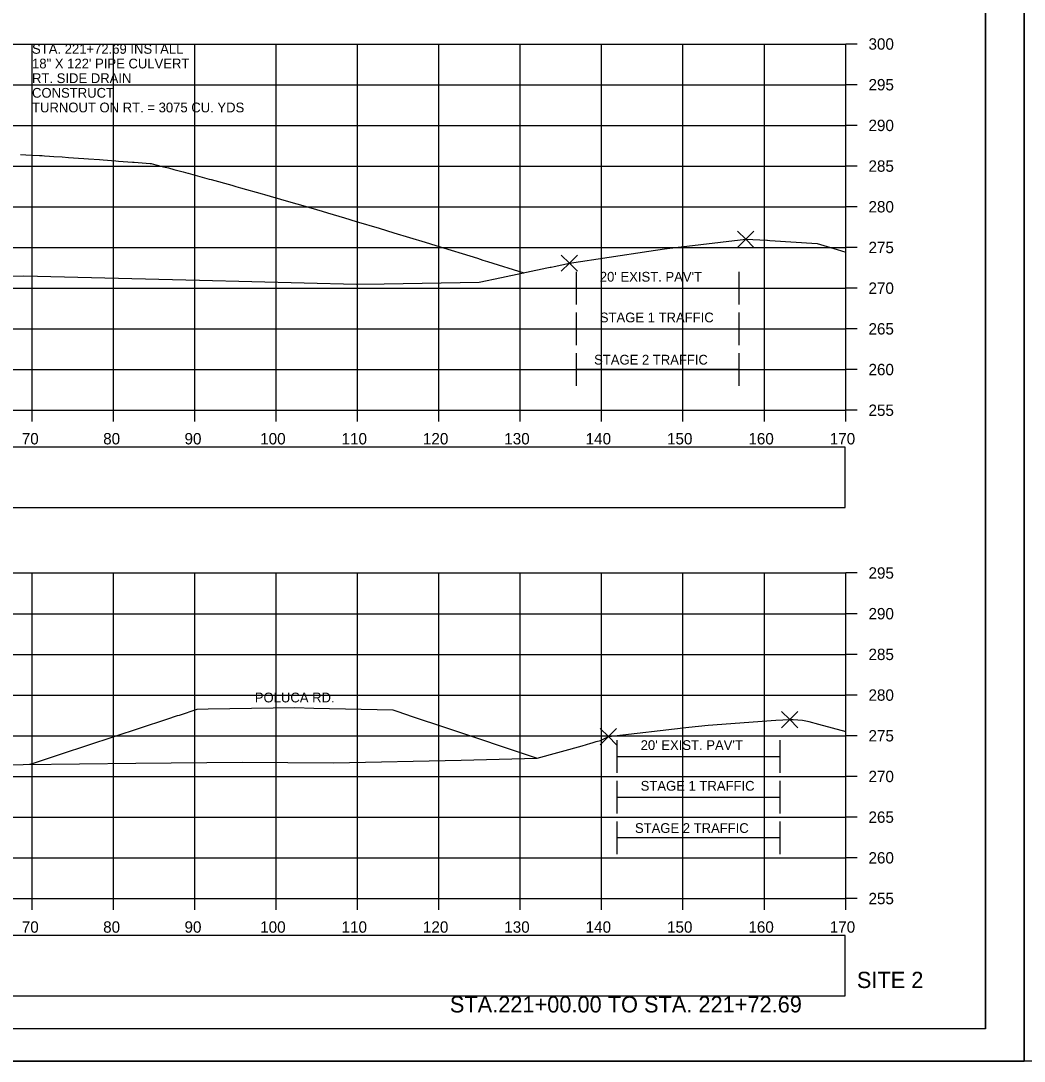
# Model space of a CAD drawing. Extents: x 4667 to 1632277, y -2100 to 724501.
# Drawn here: x 5845.8 to 5969.1, y -683.7 to -555.9 of the extents above; entities that cross this region are included whole.
import ezdxf

# ---------------------------------------------------------------- set-up
doc = ezdxf.new("R2010")
doc.units = 0
for name, color, linetype in [('R_Axis', 7, 'Continuous'), ('R_Axis Annot', 7, 'Continuous'), ('R_Border', 7, 'Continuous'), ('R_Draft', 7, 'Continuous'), ('R_Drive', 7, 'Continuous'), ('R_Exist Surface', 7, 'Continuous'), ('R_Fin Surface', 7, 'Continuous'), ('R_Grid', 7, 'Continuous'), ('R_No Plot', 7, 'Continuous'), ('R_Proposed CofA', 7, 'Continuous'), ('R_Temp Easement', 7, 'Continuous'), ('R_Water Annot', 7, 'Continuous')]:
    doc.layers.add(name, color=color, linetype=linetype)

msp = doc.modelspace()

# ---------------------------------------------------------------- linework, layer by layer
at = {"layer": 'R_Axis'}
for p, q in [((5947.18, -603.75), (5947.18, -558.75)), ((5948.58, -558.75), (5947.18, -558.75)), ((5948.58, -563.75), (5947.18, -563.75)), ((5948.58, -568.75), (5947.18, -568.75)), ((5948.58, -573.75), (5947.18, -573.75)), ((5948.58, -578.75), (5947.18, -578.75)), ((5948.58, -583.75), (5947.18, -583.75)), ((5948.58, -588.75), (5947.18, -588.75)), ((5948.58, -593.75), (5947.18, -593.75)), ((5948.58, -598.75), (5947.18, -598.75)), ((5667.18, -603.75), (5947.18, -603.75)), ((5847.18, -605.15), (5847.18, -603.75)), ((5857.18, -605.15), (5857.18, -603.75)), ((5867.18, -605.15), (5867.18, -603.75)), ((5877.18, -605.15), (5877.18, -603.75)), ((5887.18, -605.15), (5887.18, -603.75)), ((5897.18, -605.15), (5897.18, -603.75)), ((5907.18, -605.15), (5907.18, -603.75)), ((5917.18, -605.15), (5917.18, -603.75)), ((5927.18, -605.15), (5927.18, -603.75)), ((5937.18, -605.15), (5937.18, -603.75)), ((5947.18, -605.15), (5947.18, -603.75)), ((5948.58, -603.75), (5947.18, -603.75)), ((5947.18, -663.75), (5947.18, -623.75)), ((5948.58, -623.75), (5947.18, -623.75)), ((5948.58, -628.75), (5947.18, -628.75)), ((5948.58, -633.75), (5947.18, -633.75)), ((5948.58, -638.75), (5947.18, -638.75)), ((5948.58, -643.75), (5947.18, -643.75)), ((5948.58, -648.75), (5947.18, -648.75)), ((5948.58, -653.75), (5947.18, -653.75)), ((5948.58, -658.75), (5947.18, -658.75)), ((5667.18, -663.75), (5947.18, -663.75)), ((5847.18, -665.15), (5847.18, -663.75)), ((5857.18, -665.15), (5857.18, -663.75)), ((5867.18, -665.15), (5867.18, -663.75)), ((5877.18, -665.15), (5877.18, -663.75)), ((5887.18, -665.15), (5887.18, -663.75)), ((5897.18, -665.15), (5897.18, -663.75)), ((5907.18, -665.15), (5907.18, -663.75)), ((5917.18, -665.15), (5917.18, -663.75)), ((5927.18, -665.15), (5927.18, -663.75)), ((5937.18, -665.15), (5937.18, -663.75)), ((5947.18, -665.15), (5947.18, -663.75)), ((5948.58, -663.75), (5947.18, -663.75))]:
    msp.add_line(p, q, dxfattribs=at)
at = {"layer": 'R_Border'}
for q in [(5964.36, -474.29), (5648.18, -679.75)]:
    msp.add_line((5964.36, -679.75), q, dxfattribs=at)
at = {"layer": 'R_Exist Surface'}
for points in [[(5835.07, -587.3), (5846.16, -587.24), (5867.78, -587.77), (5887.04, -588.25), (5890.46, -588.21), (5902.14, -588), (5904.89, -587.46), (5910.43, -586.27), (5910.85, -586.19), (5910.97, -586.17), (5911.35, -586.08), (5913.23, -585.68), (5922.98, -584.22), (5924.91, -583.91), (5926.25, -583.74), (5934.89, -582.75), (5937.48, -582.86), (5937.56, -582.86), (5937.86, -582.89), (5943.68, -583.26), (5946.15, -584), (5947.18, -584.32)], [(5798.09, -647.78), (5846.08, -647.27), (5859.94, -647.13), (5872.99, -647), (5884.22, -647.07), (5899.91, -646.74), (5909.27, -646.51), (5914.78, -644.99), (5915.85, -644.64), (5916.02, -644.61), (5916.51, -644.47), (5917.06, -644.32), (5918.01, -643.86), (5927.91, -642.7), (5930.26, -642.43), (5938.61, -641.85), (5940.3, -641.76), (5940.71, -641.76), (5941.88, -641.83), (5942.49, -641.97), (5942.66, -642.01), (5943.85, -642.34), (5947.18, -643.21)]]:
    msp.add_lwpolyline(points, dxfattribs=at)
at = {"layer": 'R_Fin Surface'}
for points in [[(5845.75, -572.31), (5846.4, -572.35), (5847.14, -572.39), (5848.11, -572.45), (5848.41, -572.47), (5848.72, -572.49), (5849.31, -572.53), (5849.87, -572.57), (5850.9, -572.63), (5851.68, -572.69), (5852.88, -572.77), (5853.55, -572.82), (5854.13, -572.86), (5855.47, -572.95), (5855.93, -572.99), (5857.47, -573.1), (5857.79, -573.13), (5859.54, -573.25), (5859.72, -573.27), (5861.69, -573.42), (5861.84, -573.43), (5862.41, -573.58), (5863.34, -573.83), (5863.93, -573.98), (5864.61, -574.16), (5865.75, -574.47), (5866.32, -574.62), (5866.35, -574.63), (5868.95, -575.34), (5869.18, -575.4), (5871.73, -576.11), (5872.21, -576.24), (5872.81, -576.41), (5875.47, -577.16), (5875.74, -577.24), (5876.45, -577.44), (5878.99, -578.18), (5880.45, -578.6), (5882.83, -579.3), (5883.49, -579.49), (5885.57, -580.11), (5887.03, -580.54), (5889.86, -581.39), (5891.66, -581.94), (5895.48, -583.1), (5896.82, -583.51), (5901.91, -585.08), (5902.6, -585.3), (5903.16, -585.47), (5907.63, -586.87)], [(5846.92, -647.26), (5847.36, -647.11), (5850.81, -645.98), (5863.76, -641.71), (5865.07, -641.28), (5865.29, -641.21), (5867.47, -640.49), (5868.81, -640.46), (5879.49, -640.28), (5881.8, -640.34), (5891.52, -640.56), (5892.13, -640.77), (5893.91, -641.37), (5897.99, -642.73), (5909.15, -646.48)]]:
    msp.add_lwpolyline(points, dxfattribs=at)
at = {"layer": 'R_Grid'}
for p, q in [((5667.18, -558.75), (5947.18, -558.75)), ((5847.18, -603.75), (5847.18, -558.75)), ((5857.18, -603.75), (5857.18, -558.75)), ((5867.18, -603.75), (5867.18, -558.75)), ((5877.18, -603.75), (5877.18, -558.75)), ((5887.18, -603.75), (5887.18, -558.75)), ((5897.18, -603.75), (5897.18, -558.75)), ((5907.18, -603.75), (5907.18, -558.75)), ((5917.18, -603.75), (5917.18, -558.75)), ((5927.18, -603.75), (5927.18, -558.75)), ((5937.18, -603.75), (5937.18, -558.75)), ((5947.18, -603.75), (5947.18, -558.75)), ((5667.18, -563.75), (5947.18, -563.75)), ((5667.18, -568.75), (5947.18, -568.75)), ((5667.18, -573.75), (5947.18, -573.75)), ((5667.18, -578.75), (5947.18, -578.75)), ((5667.18, -583.75), (5947.18, -583.75)), ((5667.18, -588.75), (5947.18, -588.75)), ((5667.18, -593.75), (5947.18, -593.75)), ((5667.18, -598.75), (5947.18, -598.75)), ((5667.18, -603.75), (5947.18, -603.75)), ((5667.18, -623.75), (5947.18, -623.75)), ((5847.18, -663.75), (5847.18, -623.75)), ((5857.18, -663.75), (5857.18, -623.75)), ((5867.18, -663.75), (5867.18, -623.75)), ((5877.18, -663.75), (5877.18, -623.75)), ((5887.18, -663.75), (5887.18, -623.75)), ((5897.18, -663.75), (5897.18, -623.75)), ((5907.18, -663.75), (5907.18, -623.75)), ((5917.18, -663.75), (5917.18, -623.75)), ((5927.18, -663.75), (5927.18, -623.75)), ((5937.18, -663.75), (5937.18, -623.75)), ((5947.18, -663.75), (5947.18, -623.75)), ((5667.18, -628.75), (5947.18, -628.75)), ((5667.18, -633.75), (5947.18, -633.75)), ((5667.18, -638.75), (5947.18, -638.75)), ((5667.18, -643.75), (5947.18, -643.75)), ((5667.18, -648.75), (5947.18, -648.75)), ((5667.18, -653.75), (5947.18, -653.75)), ((5667.18, -658.75), (5947.18, -658.75)), ((5667.18, -663.75), (5947.18, -663.75))]:
    msp.add_line(p, q, dxfattribs=at)
at = {"layer": 'R_No Plot'}
msp.add_line((5635.78, -683.73), (5969.12, -683.73), dxfattribs=at)
for points in [[(5635.78, -470.4), (5969.12, -470.4), (5969.12, -683.74), (5635.78, -683.74)], [(5969.12, -470.4), (6302.46, -470.4), (6302.46, -683.74), (5969.12, -683.74)], [(5882.1, -474.29), (5901.72, -474.29), (5901.72, -484.17), (5917.84, -484.17), (5941.04, -484.17), (5941.04, -508.51), (5964.36, -508.51), (5964.36, -679.75), (5648.18, -679.75), (5648.18, -474.29)]]:
    msp.add_lwpolyline(points, close=True, dxfattribs=at)
for points in [[(5934.89, -582.75), (5933.89, -581.75), (5934.89, -582.75), (5933.89, -583.75), (5934.89, -582.75), (5935.89, -583.75), (5934.89, -582.75), (5935.89, -581.75)], [(5913.23, -585.68), (5912.23, -584.68), (5913.23, -585.68), (5912.23, -586.68), (5913.23, -585.68), (5914.23, -586.68), (5913.23, -585.68), (5914.23, -584.68)], [(5940.3, -641.76), (5939.3, -640.76), (5940.3, -641.76), (5939.3, -642.76), (5940.3, -641.76), (5941.3, -642.76), (5940.3, -641.76), (5941.3, -640.76)], [(5918.01, -643.86), (5917.01, -642.86), (5918.01, -643.86), (5917.01, -644.86), (5918.01, -643.86), (5919.01, -644.86), (5918.01, -643.86), (5919.01, -642.86)]]:
    msp.add_lwpolyline(points, dxfattribs=at)
at = {"layer": 'R_Proposed CofA'}
for points in [[(5667.23, -615.7), (5947.13, -615.7), (5947.13, -608.28), (5667.23, -608.28)], [(5667.23, -675.7), (5947.13, -675.7), (5947.13, -668.28), (5667.23, -668.28)]]:
    msp.add_lwpolyline(points, close=True, dxfattribs=at)
at = {"layer": 'R_Temp Easement'}
for p, q in [((5914.1, -590.75), (5914.1, -586.75)), ((5934.1, -590.75), (5934.1, -586.75)), ((5914.1, -588.75), (5934.1, -588.75)), ((5914.1, -595.75), (5914.1, -591.75)), ((5934.1, -595.75), (5934.1, -591.75)), ((5914.1, -593.75), (5934.1, -593.75)), ((5914.1, -600.75), (5914.1, -596.75)), ((5934.1, -600.75), (5934.1, -596.75)), ((5934.1, -598.75), (5914.1, -598.75)), ((5919.11, -648.3), (5919.11, -644.3)), ((5939.11, -648.3), (5939.11, -644.3)), ((5919.11, -646.3), (5939.11, -646.3)), ((5919.11, -653.3), (5919.11, -649.3)), ((5939.11, -653.3), (5939.11, -649.3)), ((5919.11, -651.3), (5939.11, -651.3)), ((5919.11, -658.3), (5919.11, -654.3)), ((5939.11, -658.3), (5939.11, -654.3)), ((5939.11, -656.3), (5919.11, -656.3))]:
    msp.add_line(p, q, dxfattribs=at)

# ---------------------------------------------------------------- texts
at = {"layer": 'R_Axis Annot'}
for s, p in [('300', (5949.98, -559.45)), ('295', (5949.98, -564.45)), ('290', (5949.98, -569.45)), ('285', (5949.98, -574.45)), ('280', (5949.98, -579.45)), ('275', (5949.98, -584.45)), ('270', (5949.98, -589.45)), ('265', (5949.98, -594.45)), ('260', (5949.98, -599.45)), ('255', (5949.98, -604.45)), ('70', (5845.92, -607.95)), ('80', (5855.92, -607.95)), ('90', (5865.92, -607.95)), ('100', (5875.22, -607.95)), ('110', (5885.22, -607.95)), ('120', (5895.22, -607.95)), ('130', (5905.22, -607.95)), ('140', (5915.22, -607.95)), ('150', (5925.22, -607.95)), ('160', (5935.22, -607.95)), ('170', (5945.22, -607.95)), ('295', (5949.98, -624.45)), ('290', (5949.98, -629.45)), ('285', (5949.98, -634.45)), ('280', (5949.98, -639.45)), ('275', (5949.98, -644.45)), ('270', (5949.98, -649.45)), ('265', (5949.98, -654.45)), ('260', (5949.98, -659.45)), ('255', (5949.98, -664.45)), ('70', (5845.92, -667.95)), ('80', (5855.92, -667.95)), ('90', (5865.92, -667.95)), ('100', (5875.22, -667.95)), ('110', (5885.22, -667.95)), ('120', (5895.22, -667.95)), ('130', (5905.22, -667.95)), ('140', (5915.22, -667.95)), ('150', (5925.22, -667.95)), ('160', (5935.22, -667.95)), ('170', (5945.22, -667.95))]:
    msp.add_text(s, height=1.4, dxfattribs=at).set_placement(p)
at = {"layer": 'R_Draft'}
for s, p in [('SITE 2', (5948.55, -674.75)), ('STA.221+00.00 TO STA. 221+72.69', (5898.53, -677.75))]:
    msp.add_text(s, height=2, dxfattribs=at).set_placement(p)
at = {"layer": 'R_Drive'}
msp.add_text('POLUCA RD.', height=1.2, dxfattribs=at).set_placement((5874.56, -639.65))
at = {"layer": 'R_Temp Easement'}
for s, height, p in [("20' EXIST. PAV'T", 1.2, (5916.96, -587.95)), ('STAGE 1 TRAFFIC', 1.2, (5916.96, -592.95)), ('STAGE 2 TRAFFIC', 1.1985, (5916.26, -598.14)), ("20' EXIST. PAV'T", 1.2, (5921.98, -645.5)), ('STAGE 1 TRAFFIC', 1.2, (5921.98, -650.5)), ('STAGE 2 TRAFFIC', 1.1985, (5921.28, -655.69))]:
    msp.add_text(s, height=height, dxfattribs=at).set_placement(p)
at = {"layer": 'R_Water Annot'}
for s, p in [('STA. 221+72.69 INSTALL', (5847.18, -559.95)), ('18" X 122\' PIPE CULVERT', (5847.18, -561.75)), ('RT. SIDE DRAIN', (5847.18, -563.55)), ('CONSTRUCT ', (5847.18, -565.35)), ('TURNOUT ON RT. = 3075 CU. YDS', (5847.18, -567.15))]:
    msp.add_text(s, height=1.2, dxfattribs=at).set_placement(p)

doc.saveas('drawing.dxf')
